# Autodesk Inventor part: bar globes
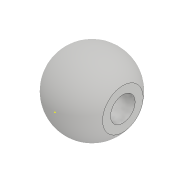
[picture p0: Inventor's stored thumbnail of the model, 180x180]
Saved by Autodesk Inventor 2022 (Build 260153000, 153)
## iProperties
Created: 2016-03
Part Number: bar globes
Material: Generic
Document SubType Name: Modeling
Designer: Sandeep
Density: 1 g/cm^3
Appearance: Default
Mass: 0.753654 g
Surface Area: 5.66286 cm^2
Volume: 0.753654 cm^3
Author: Sandeep
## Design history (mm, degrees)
sketch "Sketch1"
  geometry: L1 (0, 12)-(0, 0); A1 r 6 centre (0, 6) between (0, 12) and (0, 0)
  constraints: 2 end point, 2 point on circle, 1 centre point, 1 midpoint, 1 vertical
revolve "Revolution1" sketch "Sketch1" stored, may be unused: angle "d1" = 90 deg
sketch "Sketch2"
  geometry: 1 further point
sketch "Sketch3"
  geometry: 1 further point
sketch "Sketch4"
  geometry: 1 further point
sketch "Sketch5"
  geometry: L1 (5.014, 9.295)-(5.014, 2.705); A1 r 6 centre (0, 6) between (0, 0) and (5.014, 9.295) reference; A2 r 6 centre (0, 6) between (0, 0) and (5.014, 2.705) reference; 2 further points
  constraints: 2 end point, 2 point on circle, 1 vertical, 1 vertical alignment
extrude "Extrusion1" cut sketch "Sketch5" stored distance "d2" = 10; taper "d3" = 0 deg
sketch "Sketch6"
  geometry: L1 (5.65, 4.164)-(5.65, -4.091); A1 r 6 centre (0, 0) between (-5.014, -3.295) and (-5.014, 3.295) reference; 1 further point
  constraints: 2 end point, 1 vertical
extrude "Extrusion2" cut sketch "Sketch6" distance "d5" = 15.75; taper "d6" = 0 deg
sketch "Sketch7"
  geometry: L1 (-5.65, 3.981)-(-5.65, 8.019) reference; L2 (-5.65, 6)-(5.014, 6); L3 (-4.986, 8)-(5.014, 8); L4 (5.014, 8)-(5.014, 6); L5 (5.014, 9.295)-(5.014, 2.705) reference; L6 (-5.65, 7.336)-(-5.65, 6); L7 (-4.986, 8)-(-5.65, 7.336); 3 further points
  constraints: 10 end point, 2 collinear, 2 horizontal, 2 midpoint, 2 point on line
  dimensions: "d16" = 4 diameter of L3 L2; "d17" = 10 distance of L3.end L3.start; "d19" = 45 deg angle of L7 L3
revolve "Revolution2" sketch "Sketch7" stored, may be unused: angle "d18" = 90 deg
body "Solid1"
other parameters: "d4" = 15.75
